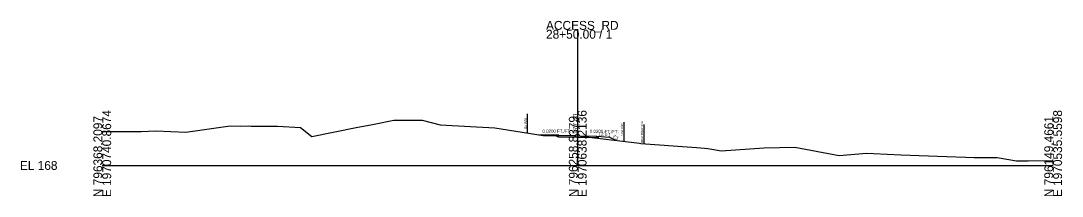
# Model space of a CAD drawing. Extents: x 27306 to 1891059, y 5381 to 776288.
# Drawn here: x 28306 to 28634.5, y 9880.7 to 9936.1 of the extents above; entities that cross this region are included whole.
import ezdxf

# ---------------------------------------------------------------- set-up
doc = ezdxf.new("R2010")
doc.units = 0
for name, color, linetype in [('RD_EX_BldgApp', 7, 'Continuous'), ('RD_EX_H2O_BlueLn', 7, 'Continuous'), ('RD_EX_RailRoad', 7, 'Continuous'), ('RD_HC_Cl', 7, 'Continuous'), ('RD_HC_Data', 7, 'Continuous'), ('RD_HC_Data_Tic', 7, 'Continuous'), ('RD_HC_TX_Sta50', 7, 'Continuous'), ('RD_PD_ALT5_CL', 7, 'Continuous'), ('RD_PD_Final_Cl', 7, 'Continuous'), ('RD_PD_Final_TrvlWay', 7, 'Continuous'), ('RD_PD_MedBWall', 7, 'Continuous'), ('RD_TX_RoadID', 7, 'Continuous')]:
    doc.layers.add(name, color=color, linetype=linetype)

msp = doc.modelspace()

# ---------------------------------------------------------------- linework, layer by layer
at = {"layer": 'RD_EX_H2O_BlueLn'}
msp.add_line((28487.65, 9899.71), (28491.65, 9899.39), dxfattribs=at)
at = {"layer": 'RD_EX_RailRoad'}
for p, q in [((28475.15, 9899.71), (28475.65, 9899.7)), ((28475.15, 9899.46), (28475.15, 9899.71)), ((28475.65, 9899.45), (28475.15, 9899.46)), ((28475.65, 9899.7), (28475.65, 9899.95)), ((28475.65, 9899.45), (28481.65, 9899.33)), ((28481.65, 9899.33), (28487.65, 9899.21)), ((28487.65, 9899.46), (28487.65, 9899.71)), ((28488.15, 9899.45), (28487.65, 9899.46)), ((28487.65, 9899.21), (28488.15, 9899.2)), ((28488.15, 9899.2), (28488.15, 9899.45))]:
    msp.add_line(p, q, dxfattribs=at)
at = {"layer": 'RD_HC_Cl'}
for p, q in [((28481.65, 9890.44), (28481.65, 9933.24)), ((28331.65, 9890.44), (28481.65, 9890.44)), ((28481.65, 9890.44), (28631.65, 9890.44))]:
    msp.add_line(p, q, dxfattribs=at)
at = {"layer": 'RD_PD_ALT5_CL'}
for p, q in [((28475.65, 9899.95), (28469.73, 9900.07)), ((28491.65, 9899.39), (28493.69, 9898.37))]:
    msp.add_line(p, q, dxfattribs=at)
at = {"layer": 'RD_PD_Final_Cl'}
msp.add_lwpolyline([(28331.65, 9901.14), (28343.91, 9901.13), (28348.57, 9901.36), (28357.98, 9900.94), (28372.02, 9902.9), (28375.23, 9902.88), (28377.65, 9902.89), (28378.58, 9902.87), (28386.96, 9902.87), (28394.18, 9902.45), (28397.76, 9899.58), (28411.8, 9902.46), (28416.95, 9903.36), (28423.59, 9904.69), (28432.57, 9904.7), (28438.28, 9903.26), (28455.52, 9902.35), (28470.78, 9899.9), (28480.8, 9899.93), (28481.65, 9899.83), (28501.13, 9897.47), (28501.57, 9897.41), (28517.65, 9896.21), (28519.12, 9896.1), (28521.62, 9895.93), (28522.71, 9895.79), (28523.98, 9895.57), (28526.89, 9895.05), (28540.44, 9895.99), (28550.13, 9896.24), (28564.13, 9893.56), (28572.74, 9894.27), (28574.97, 9894.19), (28583.56, 9893.79), (28598.14, 9893.29), (28604.1, 9893.04), (28606.74, 9893), (28608.5, 9892.95), (28614.02, 9892.92), (28620.03, 9891.9), (28623.76, 9891.92), (28629.57, 9891.96), (28631.65, 9891.92)], dxfattribs=at)
at = {"layer": 'RD_PD_Final_TrvlWay'}
msp.add_line((28465.74, 9906.75), (28465.74, 9900.75), dxfattribs=at)
at = {"layer": 'RD_PD_MedBWall'}
for p, q in [((28475.65, 9899.95), (28481.65, 9899.83)), ((28481.65, 9899.83), (28487.65, 9899.71))]:
    msp.add_line(p, q, dxfattribs=at)
at = {"layer": 'RD_TX_RoadID'}
for p, q in [((28496.18, 9904.05), (28496.18, 9898.05)), ((28502.55, 9903.37), (28502.55, 9897.37))]:
    msp.add_line(p, q, dxfattribs=at)

# ---------------------------------------------------------------- texts
at = {"layer": 'RD_EX_BldgApp'}
msp.add_text('177.39', height=0.8, rotation=90, dxfattribs=at).set_placement((28482.35, 9901.84))
at = {"layer": 'RD_HC_Cl'}
for s, p in [('ACCESS_RD', (28471.65, 9933.24)), ('28+50.00 / 1', (28471.65, 9930.44)), ('EL 168', (28305.65, 9889.04))]:
    msp.add_text(s, height=2.8, dxfattribs=at).set_placement(p)
for s, p in [('N 796368.2097', (28331.65, 9880.44)), ('E 1970740.8674', (28334.45, 9880.44)), ('N 796258.8379', (28481.65, 9880.44)), ('E 1970638.2136', (28484.45, 9880.44)), ('N 796149.4661', (28631.65, 9880.44)), ('E 1970535.5598', (28634.45, 9880.44))]:
    msp.add_text(s, height=2.8, rotation=90, dxfattribs=at).set_placement(p)
at = {"layer": 'RD_HC_Data'}
msp.add_text(' 177.40', height=1.5, rotation=90, dxfattribs=at).set_placement((28481.65, 9899.83))
at = {"layer": 'RD_HC_Data_Tic'}
msp.add_text('12.5:1', height=1, rotation=355.4261, dxfattribs=at).set_placement((28488.19, 9899.92))
at = {"layer": 'RD_HC_TX_Sta50'}
for s, rotation, p in [('0.0200 FT./FT.', 0.3916, (28470.53, 9900.76)), ('0.0200 FT./FT.', 358.8542, (28485.47, 9900.76)), ('2:1', 331.3922, (28492.59, 9899.37))]:
    msp.add_text(s, height=1, rotation=rotation, dxfattribs=at).set_placement(p)
at = {"layer": 'RD_PD_Final_TrvlWay'}
msp.add_text('Ex. R/W ', height=0.65, rotation=90, dxfattribs=at).set_placement((28465.49, 9902.13))
at = {"layer": 'RD_TX_RoadID'}
for s, p in [('NEW R/W ', (28495.91, 9899.61)), ('NEW TEMP R/W ', (28502.28, 9897.58))]:
    msp.add_text(s, height=0.65, rotation=90, dxfattribs=at).set_placement(p)

doc.saveas('drawing.dxf')
